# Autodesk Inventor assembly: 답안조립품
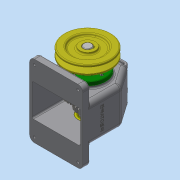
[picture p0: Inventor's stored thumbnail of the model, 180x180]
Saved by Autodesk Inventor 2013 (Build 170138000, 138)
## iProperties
Created: 2016-12
Part Number: 답안조립품
Document SubType Name: Assembly
Designer: dgall
Author: dgall
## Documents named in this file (15)
- C:\Users\dgall\Desktop\461207V1017\답안조립품.iam
- C:\Users\dgall\Desktop\461207V1017\본체.ipt
- C:\Users\dgall\Desktop\461207V1017\V-벨트풀리.ipt
- C:\Users\dgall\Desktop\461207V1017\뒤커버.ipt
- C:\Users\dgall\Desktop\461207V1017\멈춤나사 - M4x10.ipt
- C:\Users\dgall\Desktop\461207V1017\베어링 6203.ipt
- C:\Users\dgall\Desktop\461207V1017\볼트 M3 x 8.ipt
- C:\Users\dgall\Desktop\461207V1017\볼트 M3 x 10.ipt
- C:\Users\dgall\Desktop\461207V1017\부시.ipt
- C:\Users\dgall\Desktop\461207V1017\스퍼기어.ipt
- C:\Users\dgall\Desktop\461207V1017\앞커버.ipt
- C:\Users\dgall\Desktop\461207V1017\오일씰 28 40 8.ipt
- C:\Users\dgall\Desktop\461207V1017\축.ipt
- C:\Users\dgall\Desktop\461207V1017\키 - 5 x 5 x 18.ipt
- C:\Users\dgall\Desktop\461207V1017\키 - 6 x 6 x 22.ipt
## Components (9 placed, 3 different names)
1. V-벨트풀리:1
2. ISO 4762 M3 x 10:1
3. ISO 4762 M3 x 10:2
4. ISO 4762 M3 x 10:3
5. ISO 4762 M3 x 10:4
6. ISO 4762 M3 x 8:1
7. ISO 4762 M3 x 8:2
8. ISO 4762 M3 x 8:3
9. ISO 4762 M3 x 8:4
